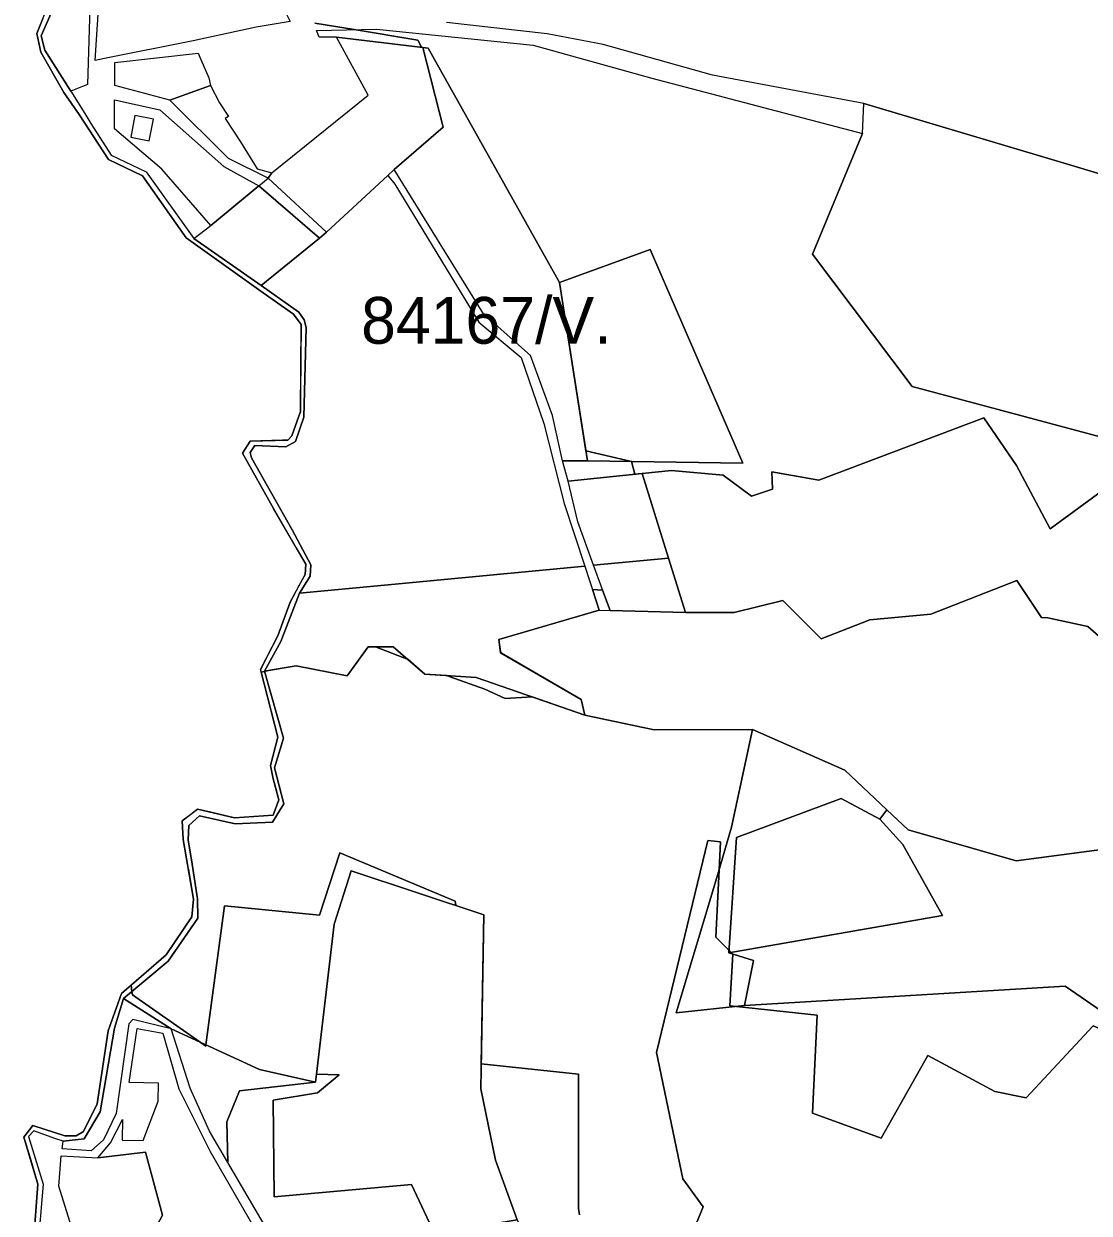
# Model space of a CAD drawing. Extents: x -477304 to -465429, y -1159113 to -1149210.
# Drawn here: x -476572.4 to -476230.8, y -1152741 to -1152359.7 of the extents above; entities that cross this region are included whole.
import ezdxf

# ---------------------------------------------------------------- set-up
doc = ezdxf.new("R2010")
doc.units = 0
for name, color, linetype in [('BPEJ_s', 7, 'Continuous'), ('orna_s', 7, 'Continuous'), ('PUPFL_s', 7, 'Continuous'), ('trav_porost_s', 7, 'Continuous'), ('voda_s', 7, 'Continuous')]:
    doc.layers.add(name, color=color, linetype=linetype)

msp = doc.modelspace()

# ---------------------------------------------------------------- linework, layer by layer
at = {"layer": 'BPEJ_s'}
for p, q in [((-476566.25, -1152357.99), (-476568.21, -1152362.8)), ((-476483.39, -1152456.15), (-476483.61, -1152478.29)), ((-476492.33, -1152515.11), (-476484.86, -1152527.95)), ((-476496.28, -1152567.61), (-476493.31, -1152566.93)), ((-476492.35, -1152601.76), (-476491.55, -1152604.83)), ((-476519.65, -1152630.51), (-476519.59, -1152630.86)), ((-476319.5, -1152709), (-476318, -1152677.5)), ((-476572.35, -1152716.66), (-476570.35, -1152723.28))]:
    msp.add_line(p, q, dxfattribs=at)
for points in [[(-476392.16, -1152496.62), (-476400.58, -1152442.67), (-476442.73, -1152367.51), (-476444.41, -1152367.31), (-476444.82, -1152367.26), (-476446, -1152365), (-476466.41, -1152361.6), (-476479, -1152359.5)], [(-476479, -1152359.5), (-476466.41, -1152361.6), (-476446, -1152365), (-476444.82, -1152367.26), (-476444.41, -1152367.31), (-476442.73, -1152367.51), (-476400.58, -1152442.67), (-476392.16, -1152496.62), (-476377.5, -1152500), (-476377.48, -1152500.07), (-476376.47, -1152504.11), (-476374.07, -1152503.86), (-476365.62, -1152531.01), (-476360.18, -1152548.47), (-476384.38, -1152547.8), (-476386.76, -1152541.25), (-476390.03, -1152541.13), (-476387.89, -1152547.69), (-476420.03, -1152557.1), (-476419.55, -1152561.05), (-476419.2, -1152561.52), (-476393.65, -1152576.3), (-476392.42, -1152581.4), (-476409.39, -1152575.52)], [(-476568.21, -1152362.8), (-476566.84, -1152368.8), (-476559.5, -1152381.74), (-476554.64, -1152388.8), (-476545.17, -1152403.24), (-476534.27, -1152408.42), (-476520.24, -1152428.38), (-476495.58, -1152445.96), (-476485.86, -1152452.83), (-476483.39, -1152456.15)], [(-476483.61, -1152478.29), (-476483.67, -1152484.07), (-476486.41, -1152491.78), (-476487.7, -1152493.21), (-476489.43, -1152493.26), (-476499.75, -1152493.56), (-476502.23, -1152497.34), (-476492.33, -1152515.11)], [(-476493.31, -1152566.93), (-476485.05, -1152565.59), (-476468.64, -1152568.73), (-476461.9, -1152559.46), (-476459.56, -1152559.45), (-476449.14, -1152563.57), (-476443.8, -1152568.23), (-476436.7, -1152568.7), (-476436, -1152569), (-476424.5, -1152573), (-476418, -1152576), (-476409.39, -1152575.52), (-476392.42, -1152581.4), (-476393.65, -1152576.3), (-476419.2, -1152561.52), (-476419.55, -1152561.05), (-476420.03, -1152557.1), (-476387.89, -1152547.69), (-476390.03, -1152541.13), (-476386.76, -1152541.25), (-476384.38, -1152547.8), (-476360.18, -1152548.47), (-476365.62, -1152531.01), (-476374.07, -1152503.86), (-476376.47, -1152504.11), (-476377.48, -1152500.07), (-476377.5, -1152500), (-476392.16, -1152496.62)], [(-476484.86, -1152527.95), (-476481.96, -1152532.94), (-476482.16, -1152536.26), (-476484.02, -1152539.74), (-476486.92, -1152545.16), (-476490.93, -1152555.9), (-476493.91, -1152561.7), (-476496.5, -1152566.74), (-476496.28, -1152567.61)], [(-476409.39, -1152575.52), (-476418, -1152576), (-476424.5, -1152573), (-476436, -1152569), (-476436.7, -1152568.7), (-476443.8, -1152568.23), (-476449.14, -1152563.57), (-476459.56, -1152559.45), (-476461.9, -1152559.46), (-476468.64, -1152568.73), (-476485.05, -1152565.59), (-476493.31, -1152566.93), (-476496.28, -1152567.61), (-476490.91, -1152588.45), (-476493.29, -1152597.54), (-476492.35, -1152601.76)], [(-476491.55, -1152604.83), (-476490.61, -1152608.48), (-476492.4, -1152613.43), (-476504.83, -1152614.25), (-476512.85, -1152612.38), (-476516.62, -1152611.5), (-476518.8, -1152613.17), (-476521.54, -1152615.27), (-476521.28, -1152621.21), (-476519.65, -1152630.51)], [(-476318, -1152677.5), (-476343.81, -1152674.73), (-476346, -1152674.5), (-476345.03, -1152657.96), (-476345.56, -1152657.44), (-476346.27, -1152656.73), (-476350.5, -1152652.5), (-476349.44, -1152630.94), (-476349, -1152622), (-476353, -1152621.5), (-476369.5, -1152689.5), (-476361, -1152730), (-476354.5, -1152739), (-476360.5, -1152753.5)], [(-476360.5, -1152753.5), (-476354.5, -1152739), (-476361, -1152730), (-476369.5, -1152689.5), (-476353, -1152621.5), (-476349, -1152622), (-476349.44, -1152630.94), (-476350.5, -1152652.5), (-476346.27, -1152656.73), (-476345.56, -1152657.44), (-476345.03, -1152657.96), (-476346, -1152674.5), (-476343.81, -1152674.73), (-476318, -1152677.5), (-476319.5, -1152709), (-476297.5, -1152717), (-476282.5, -1152690.5), (-476261, -1152702), (-476251, -1152704), (-476229.5, -1152681), (-476207, -1152690.5), (-476189, -1152702.5), (-476194, -1152782.5)], [(-476394.13, -1152741.56), (-476394.5, -1152739.5), (-476394.5, -1152696.5), (-476425.69, -1152693.14), (-476424.8, -1152645.4), (-476433.81, -1152642.42), (-476434, -1152641), (-476471, -1152625.5), (-476477.5, -1152645.5), (-476508, -1152642.5), (-476513.94, -1152687.08), (-476514, -1152687.5), (-476515.84, -1152686.21), (-476537.5, -1152671), (-476537.66, -1152669.95), (-476537.97, -1152667.92), (-476541.02, -1152670.55), (-476545.29, -1152682.61), (-476548.82, -1152705.97), (-476553.2, -1152714.84), (-476555.58, -1152716.18), (-476559.19, -1152716.23), (-476569.47, -1152712.94), (-476572.35, -1152716.66)], [(-476519.59, -1152630.86), (-476517.93, -1152640.35), (-476518.42, -1152646.02), (-476526.72, -1152658.22), (-476537.97, -1152667.92), (-476537.66, -1152669.95), (-476537.5, -1152671), (-476515.84, -1152686.21), (-476514, -1152687.5), (-476513.94, -1152687.08), (-476508, -1152642.5), (-476477.5, -1152645.5), (-476471, -1152625.5), (-476434, -1152641), (-476433.81, -1152642.42), (-476424.8, -1152645.4), (-476425.69, -1152693.14), (-476394.5, -1152696.5), (-476394.5, -1152739.5), (-476394.13, -1152741.56)], [(-476194, -1152782.5), (-476189, -1152702.5), (-476207, -1152690.5), (-476229.5, -1152681), (-476251, -1152704), (-476261, -1152702), (-476282.5, -1152690.5), (-476297.5, -1152717), (-476319.5, -1152709)], [(-476570.35, -1152723.28), (-476567.81, -1152731.72), (-476569.91, -1152758.93)]]:
    msp.add_lwpolyline(points, dxfattribs=at)
at = {"layer": 'orna_s'}
msp.add_lwpolyline([(-476424.8, -1152645.4), (-476425.84, -1152701.17), (-476421.11, -1152723.99), (-476414.17, -1152743.15), (-476440.62, -1152747.55), (-476448.07, -1152731.86), (-476492.05, -1152735.81), (-476492.35, -1152704.81), (-476478.13, -1152702.4), (-476471.19, -1152696.63), (-476478.48, -1152696.5), (-476472.81, -1152648.4), (-476467.38, -1152631.32)], close=True, dxfattribs=at)
at = {"layer": 'PUPFL_s'}
for points in [[(-476218.87, -1152503.78), (-476243.3, -1152521.63), (-476254.06, -1152501.29), (-476264.55, -1152486.07), (-476317.48, -1152506.05), (-476332.48, -1152503.36), (-476332.31, -1152508.91), (-476339.06, -1152511.12), (-476348.14, -1152504.4), (-476364.73, -1152502.88), (-476374.07, -1152503.86), (-476397.84, -1152506.36), (-476399.64, -1152499.86), (-476391.65, -1152499.88), (-476341.82, -1152500.56), (-476371.48, -1152432.13), (-476400.58, -1152442.67), (-476442.73, -1152367.51), (-476444.41, -1152367.31), (-476472.06, -1152364.04), (-476477.68, -1152364.02), (-476478.54, -1152361.83), (-476459.21, -1152361.46), (-476409, -1152366.63), (-476370.99, -1152377.15), (-476303.4, -1152394.86), (-476319.49, -1152433.59), (-476287.51, -1152475.98), (-476193.65, -1152501.15)], [(-476208.09, -1152413.57), (-476237.68, -1152404.74), (-476302.97, -1152385.29), (-476351.55, -1152376.21), (-476386.63, -1152366.36), (-476404.5, -1152362.91), (-476436.83, -1152359.28)], [(-476193.65, -1152501.15), (-476287.51, -1152475.98), (-476319.49, -1152433.59), (-476303.4, -1152394.86), (-476302.97, -1152385.29), (-476237.68, -1152404.74), (-476208.09, -1152413.57)], [(-476222.64, -1152560.45), (-476231.18, -1152552.91), (-476244.02, -1152550.14), (-476246.01, -1152550.11), (-476253.95, -1152538.15), (-476281.49, -1152548.94), (-476301.11, -1152550.79), (-476316.68, -1152556.89), (-476329.02, -1152544.56), (-476344.64, -1152548.43), (-476360.18, -1152548.47), (-476365.62, -1152531.01), (-476374.07, -1152503.86), (-476364.73, -1152502.88), (-476348.14, -1152504.4), (-476339.06, -1152511.12), (-476332.31, -1152508.91), (-476332.48, -1152503.36), (-476317.48, -1152506.05), (-476264.55, -1152486.07), (-476254.06, -1152501.29), (-476243.3, -1152521.63), (-476218.87, -1152503.78)], [(-476216.24, -1152623.05), (-476254.22, -1152628.1), (-476288.79, -1152618.16), (-476295.6, -1152611.77), (-476309.14, -1152599.02), (-476338.74, -1152585.97), (-476370.19, -1152586.02), (-476392.42, -1152581.4), (-476393.65, -1152576.3), (-476419.51, -1152561.34), (-476420.03, -1152557.1), (-476387.89, -1152547.69), (-476384.38, -1152547.8), (-476360.18, -1152548.47), (-476344.64, -1152548.43), (-476329.02, -1152544.56), (-476316.68, -1152556.89), (-476301.11, -1152550.79), (-476281.49, -1152548.94), (-476253.95, -1152538.15), (-476246.01, -1152550.11), (-476244.02, -1152550.14), (-476231.18, -1152552.91), (-476222.64, -1152560.45)], [(-476414.17, -1152743.15), (-476421.11, -1152723.99), (-476425.84, -1152701.17), (-476424.8, -1152645.4), (-476467.38, -1152631.32), (-476472.81, -1152648.4), (-476478.48, -1152696.5), (-476478.78, -1152699.07), (-476496.75, -1152694.98), (-476525.13, -1152681.94), (-476540.33, -1152672.2), (-476526.11, -1152660.19), (-476516.55, -1152646.43), (-476516.62, -1152640.28), (-476518.33, -1152629.16), (-476519.66, -1152621.3), (-476519.41, -1152616.77), (-476515.99, -1152613.66), (-476504.61, -1152616.22), (-476492.66, -1152615.69), (-476488.94, -1152609.78), (-476491.98, -1152598.23), (-476489.13, -1152588.72), (-476495.13, -1152567.22), (-476485.05, -1152565.59), (-476468.64, -1152568.73), (-476461.9, -1152559.46), (-476453.89, -1152559.43), (-476443.8, -1152568.23), (-476427.29, -1152569.32), (-476392.42, -1152581.4), (-476370.19, -1152586.02), (-476338.74, -1152585.97), (-476345.44, -1152617.31), (-476349.84, -1152632.3), (-476363.22, -1152676.83), (-476341.26, -1152674.46), (-476310.99, -1152672.67), (-476238.45, -1152668.27), (-476225.14, -1152677.39)]]:
    msp.add_lwpolyline(points, dxfattribs=at)
for points in [[(-476371.48, -1152432.13), (-476341.82, -1152500.56), (-476391.65, -1152499.88), (-476400.58, -1152442.67)], [(-476349.84, -1152632.3), (-476345.44, -1152617.31), (-476338.74, -1152585.97), (-476309.14, -1152599.02), (-476295.6, -1152611.77), (-476297.86, -1152614.72), (-476310.29, -1152608.12), (-476343.87, -1152620.56), (-476346.33, -1152657.57), (-476338.36, -1152659.97), (-476341.26, -1152674.46), (-476363.22, -1152676.83)], [(-476346.33, -1152657.57), (-476343.87, -1152620.56), (-476310.29, -1152608.12), (-476297.86, -1152614.72), (-476290.51, -1152622.88), (-476277.75, -1152645.57)], [(-476225.14, -1152677.39), (-476238.45, -1152668.27), (-476310.99, -1152672.67), (-476341.26, -1152674.46), (-476338.36, -1152659.97), (-476346.33, -1152657.57), (-476277.75, -1152645.57), (-476290.51, -1152622.88), (-476297.86, -1152614.72), (-476295.6, -1152611.77), (-476288.79, -1152618.16), (-476254.22, -1152628.1), (-476216.24, -1152623.05), (-476201.84, -1152622.66), (-476179.33, -1152624.9), (-476117.87, -1152628.54), (-476103.01, -1152629.57), (-476100.34, -1152652.08), (-476117.93, -1152710.76), (-476145.04, -1152705.66)], [(-476525.13, -1152681.94), (-476537.39, -1152678.97), (-476538.68, -1152680.29), (-476542.71, -1152709.03), (-476546.75, -1152717.53), (-476550.73, -1152721), (-476560.02, -1152720.44), (-476559.73, -1152717.99), (-476552.96, -1152717.2), (-476547.86, -1152708.52), (-476543.24, -1152681.66), (-476540.33, -1152672.2)], [(-476518.99, -1152701), (-476525.13, -1152681.94), (-476496.75, -1152694.98), (-476478.78, -1152699.07), (-476503.24, -1152701.75), (-476507.22, -1152711.78), (-476506.9, -1152724.73), (-476512.77, -1152714.73)]]:
    msp.add_lwpolyline(points, close=True, dxfattribs=at)
at = {"layer": 'trav_porost_s'}
for points in [[(-476503.94, -1152295.64), (-476500.16, -1152306.68), (-476493.08, -1152334.64), (-476492.77, -1152347.08), (-476486.9, -1152358.98), (-476497.8, -1152360.84), (-476518.06, -1152365.19), (-476546.51, -1152370.87), (-476549.48, -1152371.46), (-476547.52, -1152341.73), (-476524.56, -1152341.88), (-476521.42, -1152341.78), (-476521.34, -1152343.33), (-476518.73, -1152343.19), (-476517.52, -1152340.82), (-476509.01, -1152336.72), (-476516.21, -1152290.48), (-476520.36, -1152285.49), (-476522.09, -1152285.66), (-476521.59, -1152295.97), (-476526.94, -1152295.64), (-476527.03, -1152285.51), (-476527.13, -1152273.57), (-476509.38, -1152286.28)], [(-476566.74, -1152363.58), (-476559.16, -1152346.31), (-476558.89, -1152336.06), (-476547.16, -1152308.79), (-476546.63, -1152306.75), (-476547.07, -1152302.49), (-476544.61, -1152302.26), (-476544.86, -1152306.38), (-476549.02, -1152326.36), (-476550.97, -1152344.94), (-476551.18, -1152354.5), (-476551.93, -1152379.15), (-476557.3, -1152381.34), (-476565.56, -1152368.23)], [(-476461.89, -1152382.58), (-476472.06, -1152364.04), (-476444.41, -1152367.31), (-476437.94, -1152392.87), (-476453.55, -1152406.48), (-476455.61, -1152408.37), (-476475.33, -1152426.5), (-476494.03, -1152409.23), (-476492.81, -1152407.49)], [(-476424.96, -1152452.75), (-476453.55, -1152406.48), (-476437.94, -1152392.87), (-476444.41, -1152367.31), (-476442.73, -1152367.51), (-476400.58, -1152442.67), (-476391.65, -1152499.88), (-476399.64, -1152499.86), (-476402.81, -1152485.31), (-476409.87, -1152466.03)], [(-476513.07, -1152377.08), (-476512.51, -1152379.56), (-476525.54, -1152384.21), (-476543.19, -1152379.54), (-476543.13, -1152372.16), (-476516.4, -1152369.15), (-476515.57, -1152371.13)], [(-476506.75, -1152389.44), (-476507.76, -1152390.11), (-476502.89, -1152397.52), (-476497.51, -1152406.22), (-476492.81, -1152407.49), (-476494.03, -1152409.23), (-476506.72, -1152402.87), (-476525.54, -1152384.21), (-476512.51, -1152379.56), (-476509.64, -1152385.04)], [(-476528.68, -1152387.29), (-476508.2, -1152405.51), (-476497.03, -1152411.71), (-476512.36, -1152424.42), (-476528.04, -1152406.38), (-476543.29, -1152393.44), (-476543.22, -1152384.09)], [(-476538.01, -1152396.1), (-476532.14, -1152397.25), (-476530.79, -1152390.28), (-476536.75, -1152389.09)], [(-476483.95, -1152542.31), (-476480.49, -1152536.82), (-476480.29, -1152533.15), (-476486.27, -1152521.99), (-476499.29, -1152498.88), (-476499.77, -1152497.11), (-476498.26, -1152494.95), (-476488.34, -1152495.35), (-476485.19, -1152493.64), (-476482.56, -1152485.87), (-476481.85, -1152457.1), (-476482.46, -1152454.6), (-476484.2, -1152452.19), (-476496.21, -1152443.67), (-476477.55, -1152428.4), (-476475.33, -1152426.5), (-476455.61, -1152408.37), (-476453.39, -1152411.09), (-476426.4, -1152455.39), (-476412.88, -1152466.71), (-476405.59, -1152487.84), (-476399.07, -1152513.5), (-476392.5, -1152533.58), (-476456.75, -1152539.73)], [(-476475.33, -1152426.5), (-476477.55, -1152428.4), (-476497.03, -1152411.71), (-476494.03, -1152409.23)], [(-476517.83, -1152428.51), (-476512.36, -1152424.42), (-476497.03, -1152411.71), (-476477.55, -1152428.4), (-476496.21, -1152443.67)], [(-476365.62, -1152531.01), (-476389.64, -1152533.31), (-476394.69, -1152519.39), (-476397.84, -1152506.36), (-476374.07, -1152503.86)], [(-476384.38, -1152547.8), (-476389.64, -1152533.31), (-476365.62, -1152531.01), (-476360.18, -1152548.47)], [(-476392.42, -1152581.4), (-476427.29, -1152569.32), (-476443.8, -1152568.23), (-476453.89, -1152559.43), (-476461.9, -1152559.46), (-476468.64, -1152568.73), (-476485.05, -1152565.59), (-476495.13, -1152567.22), (-476489.93, -1152557.8), (-476483.95, -1152542.31), (-476456.75, -1152539.73), (-476392.5, -1152533.58), (-476387.89, -1152547.69), (-476420.03, -1152557.1), (-476419.51, -1152561.34), (-476393.65, -1152576.3)], [(-476548.59, -1152723.31), (-476544.56, -1152718.44), (-476540.67, -1152711.02), (-476540.77, -1152717.6), (-476534.04, -1152717.7), (-476529.22, -1152705.14), (-476529.13, -1152699.31), (-476538.59, -1152699.17), (-476535.98, -1152681.79), (-476527.8, -1152683.3), (-476522.62, -1152701.2), (-476512.6, -1152721.2), (-476492.61, -1152755.92), (-476497.26, -1152770.21), (-476497.12, -1152796.4), (-476548.94, -1152788.49), (-476550.67, -1152780.67), (-476551.29, -1152769.3), (-476541.24, -1152766.75), (-476527.91, -1152741.71), (-476533.3, -1152721.51)], [(-476503.24, -1152701.75), (-476478.78, -1152699.07), (-476478.48, -1152696.5), (-476471.19, -1152696.63), (-476478.13, -1152702.4), (-476492.35, -1152704.81), (-476492.05, -1152735.81), (-476448.07, -1152731.86), (-476440.62, -1152747.55), (-476414.17, -1152743.15), (-476410.09, -1152752.63), (-476459.47, -1152753.78), (-476489.28, -1152754.92), (-476496.31, -1152742.79), (-476506.9, -1152724.73), (-476507.22, -1152711.78)], [(-476552.44, -1152760.14), (-476561.07, -1152732.37), (-476560.33, -1152722.68), (-476548.59, -1152723.31), (-476533.3, -1152721.51), (-476527.91, -1152741.71), (-476541.24, -1152766.75), (-476551.29, -1152769.3)]]:
    msp.add_lwpolyline(points, close=True, dxfattribs=at)
at = {"layer": 'voda_s'}
for points in [[(-476569.91, -1152758.93), (-476567.81, -1152731.72), (-476572.35, -1152716.66), (-476569.47, -1152712.94), (-476559.19, -1152716.23), (-476555.58, -1152716.18), (-476553.2, -1152714.84), (-476548.82, -1152705.97), (-476545.29, -1152682.61), (-476541.02, -1152670.55), (-476526.72, -1152658.22), (-476518.42, -1152646.02), (-476517.93, -1152640.35), (-476521.28, -1152621.21), (-476521.54, -1152615.27), (-476516.62, -1152611.5), (-476504.83, -1152614.25), (-476492.4, -1152613.43), (-476490.61, -1152608.48), (-476492.35, -1152601.76), (-476493.29, -1152597.54), (-476490.91, -1152588.45), (-476496.5, -1152566.74), (-476490.93, -1152555.9), (-476486.92, -1152545.16), (-476482.16, -1152536.26), (-476481.96, -1152532.94), (-476492.33, -1152515.11), (-476502.23, -1152497.34), (-476499.75, -1152493.56), (-476487.7, -1152493.21), (-476486.41, -1152491.78), (-476483.67, -1152484.07), (-476483.39, -1152456.15), (-476485.86, -1152452.83), (-476495.58, -1152445.96), (-476520.24, -1152428.38), (-476534.27, -1152408.42), (-476545.17, -1152403.24), (-476554.64, -1152388.8), (-476559.5, -1152381.74), (-476566.84, -1152368.8), (-476568.21, -1152362.8), (-476560.98, -1152345.04)], [(-476559.16, -1152346.31), (-476566.74, -1152363.58), (-476565.56, -1152368.23), (-476557.3, -1152381.34), (-476552.79, -1152388.49), (-476550.81, -1152391.64), (-476544.3, -1152401.89), (-476533.08, -1152407.19), (-476517.83, -1152428.51), (-476496.21, -1152443.67), (-476484.2, -1152452.19), (-476482.46, -1152454.6), (-476481.85, -1152457.1), (-476482.56, -1152485.87), (-476485.19, -1152493.64), (-476488.34, -1152495.35), (-476498.26, -1152494.95), (-476499.77, -1152497.11), (-476499.29, -1152498.88), (-476486.27, -1152521.99), (-476480.29, -1152533.15), (-476480.49, -1152536.82), (-476483.95, -1152542.31), (-476489.93, -1152557.8), (-476495.13, -1152567.22), (-476489.13, -1152588.72), (-476491.98, -1152598.23), (-476488.94, -1152609.78), (-476492.66, -1152615.69), (-476504.61, -1152616.22), (-476515.99, -1152613.66), (-476519.41, -1152616.77), (-476519.66, -1152621.3), (-476518.33, -1152629.16), (-476516.62, -1152640.28), (-476516.55, -1152646.43), (-476526.11, -1152660.19), (-476540.33, -1152672.2), (-476543.24, -1152681.66), (-476547.86, -1152708.52), (-476552.96, -1152717.2), (-476559.73, -1152717.99), (-476562.37, -1152717.06), (-476569.14, -1152714.66), (-476570.87, -1152716.42), (-476566.13, -1152731.75), (-476568.49, -1152759.38)]]:
    msp.add_lwpolyline(points, dxfattribs=at)

# ---------------------------------------------------------------- texts
at = {"layer": 'BPEJ_s'}
msp.add_text('84167/V.', height=15, dxfattribs=at).set_placement((-476464.2, -1152462.29))

doc.saveas('drawing.dxf')
